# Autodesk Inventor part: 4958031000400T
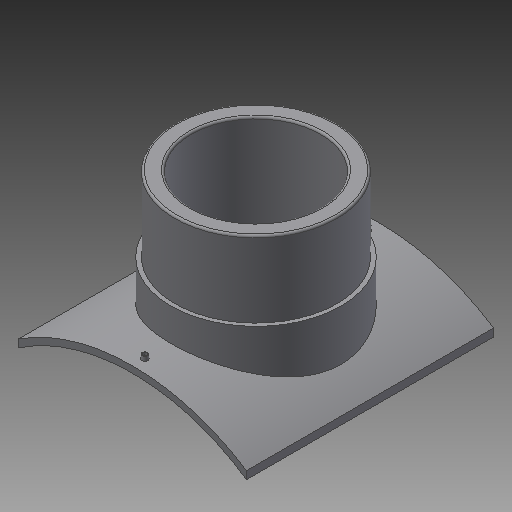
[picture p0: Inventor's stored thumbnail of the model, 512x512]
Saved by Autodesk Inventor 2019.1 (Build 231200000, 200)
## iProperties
Created: 2017-10
Part Number: 4958031000400T
Material: Generic
Document SubType Name: Modeling
Designer: KIM
Density: 1 g/cm^3
Appearance: Default
Description: PLASSON BRANCH SADDLE 1000x400
Mass: 2754.05 g
Surface Area: 3037.44 cm^2
Volume: 2754.05 cm^3
Author: KIM
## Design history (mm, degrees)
sketch "Sketch1"
  geometry: L1 (-281.5, 432.451)-(-281.5, 413.228); L2 (281.5, 432.451)-(281.5, 413.228); A1 r 500 centre (0, 0) between (281.5, 413.228) and (-281.5, 413.228); A2 r 516 centre (0, 0) between (281.5, 432.451) and (-281.5, 432.451); A3 r 500 centre (0, 0) between (281.5, 413.228) and (-281.5, 413.228); A4 r 516 centre (0, 0) between (281.5, 432.451) and (-281.5, 432.451); 1 further point
  constraints: 8 point on circle, 4 centre point, 4 end point, 2 concentric, 2 parallel, 1 coincident, 1 vertical
  dimensions: "d0" = 1000 diameter of A1 (= d_); "d1" = 16 radial gap between concentric circles of A1 A2 (= x_); "d2" = 563 distance between parallel lines of L2 L1 (derived)
extrude "Extrusion1" new body sketch "Sketch1" stored distance "d3" = 610 (= L_); taper "d4" = 0 deg
workplane "Work Plane1"
sketch "Sketch4"
  geometry: C1 r 7 at (0, 274.5); 1 further point
  constraints: 1 centre point
  dimensions: "d13" = 14 diameter of C1; "d14" = 274.5 distance of point (0, 0) C1.centre (= 0.45 x L_)
extrude "Extrusion4" join sketch "Sketch4" stored distance "d15" = 152.5 (= 0.25 x L_); taper "d16" = 5 deg
sketch "Sketch5"
  geometry: C1 r 7 at (0, 0) reference; C2 r 5 at (0, 0); C3 r 2 at (0, 0); 1 further point
  constraints: 2 centre point, 2 coincident
  dimensions: "d17" = 10 diameter of C2; "d18" = 4 diameter of C3
extrude "Extrusion5" cut sketch "Sketch5" distance "d19" = 14; taper "d20" = 0 deg
sketch "Sketch6"
  geometry: C1 r 2 at (0, 0) reference; 1 further point
extrude "Extrusion6" cut sketch "Sketch6" distance "d21" = 3; taper "d22" = 0 deg
mirror "Mirror2"
workplane "Work Plane2"
sketch "Sketch7"
  geometry: C1 r 210 at (0, 0); C2 r 8 at (0, 0); C3 r 160 at (0, 0); 1 further point
  constraints: 3 centre point, 3 coincident
  dimensions: "d24" = 420 diameter of C1 (= 1.05 x d_1); "d25" = 16 diameter of C2 (= D_); "d26" = 320 diameter of C3 (= 0.8 x d_1)
extrude "Extrusion7" join sketch "Sketch7" stored distance "d27" = 3; taper "d28" = 0 deg
sketch "Sketch8"
  geometry: C1 r 4.8 at (0, 0); 1 further point
  constraints: 1 centre point, 1 coincident
  dimensions: "d29" = 9.6 diameter of C1 (= 0.6 x D_)
extrude "Extrusion8" cut sketch "Sketch8" extent not by distance; stored distance "d30" = 3; taper "d31" = 0 deg
sketch "Sketch9"
  geometry: C1 r 4.8 at (0, 0) reference; C2 r 8 at (0, 0) reference; 1 further point
extrude "Extrusion9" cut sketch "Sketch9" distance "d32" = 133.5 (= 0.5 x H_); taper "d33" = 0 deg
fillet "Fillet2" dims "d34" = 10 (= 0.01 x d_)
sketch "Sketch10"
  geometry: C1 r 210 at (0, 0) reference; C2 r 200 at (0, 0); 1 further point
  constraints: 1 centre point, 1 coincident
  dimensions: "d36" = 400 diameter of C2 (= d_1)
extrude "Extrusion10" cut sketch "Sketch10" distance "d37" = 186.9 (derived); taper "d38" = 0 deg
fillet "Fillet4" dims "d39" = 5 (= 0.005 x d_)
sketch "Sketch2"
  geometry: L1 (-281.5, 432.451)-(-281.5, 413.228) reference; L2 (281.5, 432.451)-(281.5, 413.228) reference; L3 (281.5, 432.451)-(281.5, 413.228) reference; L4 (-8, 649.5)-(-4.8, 649.5) reference; L5 (-4.8, 649.5)-(-4.8, 499.977) reference; L6 (-210, 471.334)-(-210, 596.1) reference; L7 (-210, 596.1)-(-200, 596.1) reference; L8 (-200, 596.1)-(-200, 778) reference; L9 (-160, 778)-(-160, 490.567) reference; L10 (-8, 515.938)-(-8, 649.5) reference; L11 (4.8, 649.5)-(8, 649.5) reference; L12 (8, 649.5)-(8, 515.938) reference; L13 (160, 490.567)-(160, 778) reference; L14 (200, 778)-(200, 596.1) reference; L15 (200, 596.1)-(210, 596.1) reference; L16 (210, 596.1)-(210, 471.334) reference; L17 (4.8, 499.977)-(4.8, 649.5) reference; L18 (-281.5, 413.228)-(-281.5, 432.451) reference; L19 (281.5, 413.228)-(281.5, 432.451) reference; L20 (-195, 783)-(-165, 783) reference; L21 (165, 783)-(195, 783) reference; A1 r 500 centre (0, 0) between (-4.8, 499.977) and (-281.5, 413.228) reference; A2 r 5 centre (-165, 778) between (-160, 778) and (-165, 783) reference; A3 r 5 centre (165, 778) between (165, 783) and (160, 778) reference; A4 r 516 centre (0, 0) between (-210, 471.334) and (-281.5, 432.451) reference; A5 r 516 centre (0, 0) between (-8, 515.938) and (-160, 490.567) reference; A6 r 516 centre (0, 0) between (160, 490.567) and (8, 515.938) reference; A7 r 516 centre (0, 0) between (281.5, 432.451) and (210, 471.334) reference; A8 r 500 centre (0, 0) between (281.5, 413.228) and (4.8, 499.977) reference; A9 r 5 centre (-195, 778) between (-195, 783) and (-200, 778) reference; A10 r 5 centre (195, 778) between (200, 778) and (195, 783) reference; 3 further points
  node "Project Cut Edges1"
body "Solid1"
node "Projected Loop2"
node "Projected Loop3"
other parameters: "d_" = 1000 [user parameter; used in 4 equation terms], "d_1" = 400 [user parameter; used in 3 equation terms], "B_" = 563 [user parameter], "H_" = 267 [user parameter; used in 2 equation terms], "L_" = 610 [user parameter; used in 3 equation terms], "x_" = 16 [user parameter; used in 2 equation terms], "d12" = 525.6 (derived), "d23" = 783 (= x_ + 0.5 x d_ + H_), "D_" = 16 [user parameter; used in 2 equation terms]
